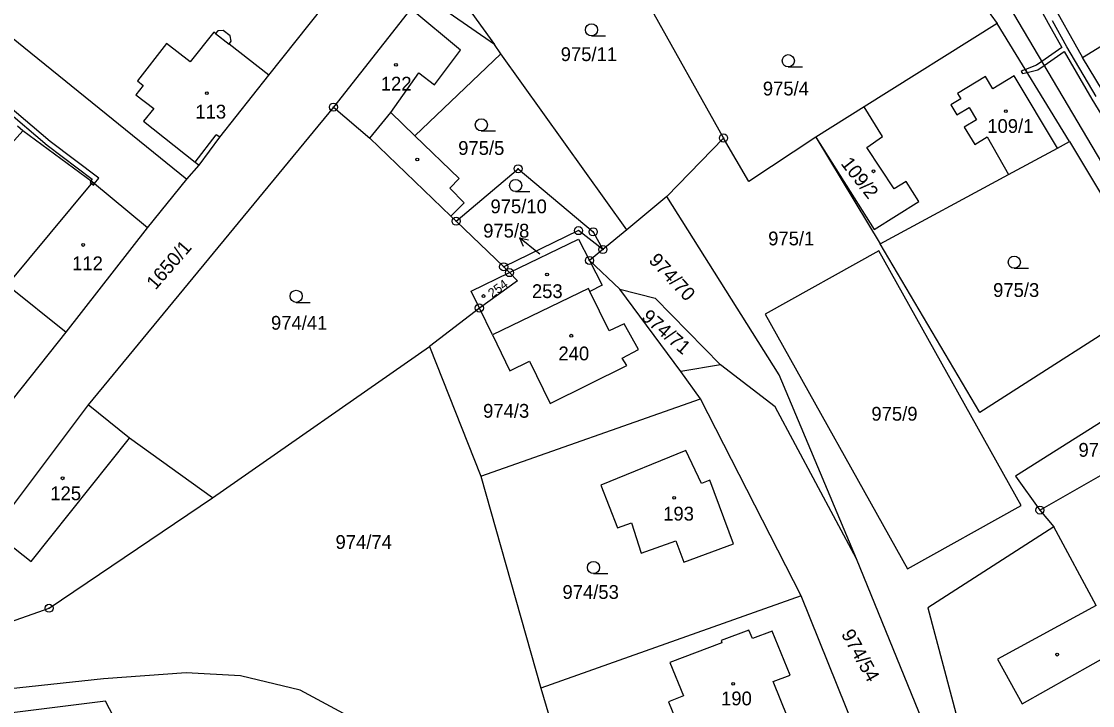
# Model space of a CAD drawing. Extents: x -680203 to -673936, y -1102717 to -1093650.
# Drawn here: x -676795.2 to -676663.1, y -1100824.1 to -1100739.7 of the extents above; entities that cross this region are included whole.
import ezdxf

# ---------------------------------------------------------------- set-up
doc = ezdxf.new("R2010")
doc.units = 0
for name, color, linetype in [('SOxx02xx_Koleje_param další_Popis10', 7, 'Continuous'), ('SOxx02xx_Staničení_Popis10', 7, 'Continuous'), ('SOxxxxxx_Koleje_hlavní_body_Popis10', 7, 'Continuous'), ('SOxxxxxx_Koleje_LN_parametry_Popis10', 7, 'Continuous'), ('SOxxxxxx_Koleje_param další_Popis10', 7, 'Continuous'), ('SOxxxxxx_Osa_bod_P', 7, 'Continuous'), ('SOxxxxxx_Staničení_Popis10', 7, 'Continuous'), ('x_prac', 7, 'Continuous')]:
    doc.layers.add(name, color=color, linetype=linetype)

msp = doc.modelspace()

# ---------------------------------------------------------------- linework, layer by layer
at = {"layer": 'SOxx02xx_Koleje_param další_Popis10'}
for centre, radius in [((-676756.77, -1100750.3), 0.5), ((-676756.77, -1100750.3), 0.0303), ((-676708.66, -1100754.11), 0.5), ((-676708.66, -1100754.11), 0.0303), ((-676733.99, -1100757.9), 0.5), ((-676733.99, -1100757.9), 0.0303), ((-676741.63, -1100764.37), 0.5), ((-676741.63, -1100764.37), 0.0303), ((-676726.54, -1100765.53), 0.5), ((-676726.54, -1100765.53), 0.0303), ((-676724.74, -1100765.68), 0.5), ((-676724.74, -1100765.68), 0.0303), ((-676723.54, -1100767.86), 0.5), ((-676725.19, -1100769.21), 0.5), ((-676723.54, -1100767.86), 0.0303), ((-676735.77, -1100769.99), 0.5), ((-676735.77, -1100769.99), 0.0303), ((-676735.05, -1100770.71), 0.5), ((-676725.19, -1100769.21), 0.0303), ((-676735.05, -1100770.71), 0.0303), ((-676738.77, -1100775.08), 0.5), ((-676738.77, -1100775.08), 0.0303), ((-676669.64, -1100800), 0.5), ((-676669.64, -1100800), 0.0303), ((-676791.84, -1100812.1), 0.5), ((-676791.84, -1100812.1), 0.0303)]:
    msp.add_circle(centre, radius, dxfattribs=at)
at = {"layer": 'SOxx02xx_Staničení_Popis10'}
for p, q in [((-676731.48, -1100768.3), (-676733.81, -1100766.41)), ((-676733.81, -1100766.41), (-676732.72, -1100766.65)), ((-676733.81, -1100766.41), (-676733.35, -1100767.43)), ((-676731.33, -1100768.42), (-676731.48, -1100768.3))]:
    msp.add_line(p, q, dxfattribs=at)
at = {"layer": 'SOxxxxxx_Koleje_hlavní_body_Popis10'}
for p, q in [((-676724.95, -1100741.52), (-676723.2, -1100741.52)), ((-676700.67, -1100745.33), (-676698.92, -1100745.33)), ((-676738.53, -1100753.23), (-676736.78, -1100753.23)), ((-676734.3, -1100760.72), (-676732.55, -1100760.72)), ((-676672.8, -1100770.18), (-676671.05, -1100770.18)), ((-676761.37, -1100774.38), (-676759.62, -1100774.38)), ((-676724.69, -1100807.82), (-676722.94, -1100807.82))]:
    msp.add_line(p, q, dxfattribs=at)
for centre in [(-676724.95, -1100740.77), (-676700.67, -1100744.58), (-676738.53, -1100752.48), (-676734.3, -1100759.97), (-676672.8, -1100769.43), (-676761.37, -1100773.63), (-676724.69, -1100807.07)]:
    msp.add_circle(centre, 0.75, dxfattribs=at)
at = {"layer": 'SOxxxxxx_Koleje_LN_parametry_Popis10'}
for points in [[(-676672.83, -1100732.25), (-676668.62, -1100739.94), (-676666.95, -1100742.94), (-676669.39, -1100744.66), (-676670.07, -1100745.13), (-676671.43, -1100745.66), (-676671.22, -1100746.01), (-676669.89, -1100745.71), (-676669.1, -1100745.15), (-676666.65, -1100743.46), (-676663.22, -1100749.32), (-676658.86, -1100756.42)], [(-676662.7, -1100749.01), (-676666.3, -1100742.87), (-676668.09, -1100739.65)], [(-676797.38, -1100750.47), (-676792.08, -1100755), (-676786.54, -1100759.19), (-676786.68, -1100759.4), (-676786.47, -1100759.55), (-676786.24, -1100759.74), (-676785.7, -1100759.07), (-676791.7, -1100754.54), (-676796.96, -1100750.05)]]:
    msp.add_lwpolyline(points, dxfattribs=at)
for points in [[(-676671.43, -1100745.66), (-676671.73, -1100745.77), (-676671.93, -1100745.89), (-676671.78, -1100746.14), (-676671.22, -1100746.01)], [(-676786.37, -1100759.91), (-676786.24, -1100759.74), (-676786.47, -1100759.55), (-676786.68, -1100759.4), (-676786.79, -1100759.58)]]:
    msp.add_lwpolyline(points, close=True, dxfattribs=at)
at = {"layer": 'SOxxxxxx_Koleje_param další_Popis10'}
for centre in [(-676749.06, -1100745.08), (-676772.38, -1100748.57), (-676673.84, -1100750.79), (-676746.43, -1100756.76), (-676690.17, -1100758.21), (-676787.63, -1100767.3), (-676730.42, -1100770.95), (-676738.26, -1100773.6), (-676727.43, -1100778.49), (-676790.17, -1100796.08), (-676714.75, -1100798.48), (-676667.52, -1100817.82), (-676707.46, -1100821.42)]:
    msp.add_circle(centre, 0.175, dxfattribs=at)
at = {"layer": 'SOxxxxxx_Staničení_Popis10'}
for p, q in [((-676741.08, -1100743.29), (-676747.24, -1100738.19)), ((-676771.3, -1100741.23), (-676769.64, -1100742.54)), ((-676744.31, -1100747.56), (-676741.08, -1100743.29)), ((-676749.71, -1100750.95), (-676746.22, -1100746.09)), ((-676746.22, -1100746.09), (-676744.31, -1100747.56)), ((-676672.83, -1100746.43), (-676675.45, -1100748.04)), ((-676667.45, -1100755.37), (-676672.83, -1100746.43)), ((-676676.36, -1100746.53), (-676679.81, -1100748.62)), ((-676675.45, -1100748.04), (-676676.36, -1100746.53)), ((-676679.81, -1100748.62), (-676679.41, -1100749.28)), ((-676679.41, -1100749.28), (-676680.64, -1100750.02)), ((-676680.64, -1100750.02), (-676679.9, -1100751.25)), ((-676679.9, -1100751.25), (-676678.37, -1100750.33)), ((-676678.37, -1100750.33), (-676677.45, -1100751.85)), ((-676752.3, -1100754.11), (-676749.71, -1100750.95)), ((-676749.71, -1100750.95), (-676746.71, -1100753.84)), ((-676677.45, -1100751.85), (-676678.97, -1100752.78)), ((-676678.97, -1100752.78), (-676677.68, -1100754.92)), ((-676773.83, -1100757.08), (-676771.23, -1100753.7)), ((-676770.77, -1100754.02), (-676771.23, -1100753.7)), ((-676677.68, -1100754.92), (-676676.13, -1100753.98)), ((-676676.13, -1100753.98), (-676673.52, -1100758.62)), ((-676786.47, -1100759.55), (-676796.99, -1100772.21)), ((-676796.99, -1100772.21), (-676789.75, -1100778.06)), ((-676794.04, -1100806.34), (-676781.93, -1100791.12)), ((-676798.77, -1100802.64), (-676794.04, -1100806.34)), ((-676662.7, -1100811.75), (-676674.85, -1100818.37)), ((-676671.83, -1100823.9), (-676659.84, -1100817.11)), ((-676674.85, -1100818.37), (-676671.83, -1100823.9))]:
    msp.add_line(p, q, dxfattribs=at)
at = {"layer": 'x_prac'}
for p, q in [((-676645.24, -1100785.51), (-676704.94, -1100684.52)), ((-676672.75, -1100729.17), (-676664.39, -1100744.2)), ((-676682.05, -1100730.15), (-676674.9, -1100740)), ((-676743.39, -1100733.54), (-676736.92, -1100742.59)), ((-676736.92, -1100742.59), (-676745.79, -1100736.42)), ((-676764.75, -1100746.35), (-676758.01, -1100737.87)), ((-676717.81, -1100737.78), (-676708.66, -1100754.11)), ((-676798.35, -1100740.16), (-676774.83, -1100759.18)), ((-676674.9, -1100740), (-676691.3, -1100750.27)), ((-676665.98, -1100754.56), (-676674.9, -1100740)), ((-676764.75, -1100746.35), (-676769.64, -1100742.54)), ((-676746.71, -1100753.84), (-676736.12, -1100743.71)), ((-676736.12, -1100743.71), (-676736.92, -1100742.59)), ((-676720.6, -1100765.42), (-676736.12, -1100743.71)), ((-676658.76, -1100753.5), (-676664.39, -1100744.2)), ((-676756.77, -1100750.3), (-676787, -1100787.02)), ((-676691.3, -1100750.27), (-676697.26, -1100753.99)), ((-676795.08, -1100753.24), (-676795.72, -1100752.64)), ((-676795.08, -1100753.24), (-676813.48, -1100773.66)), ((-676708.66, -1100754.11), (-676715.65, -1100761.31)), ((-676697.26, -1100753.99), (-676689.32, -1100767.17)), ((-676774.83, -1100759.18), (-676773.33, -1100757.46)), ((-676741.63, -1100764.37), (-676733.99, -1100757.9)), ((-676733.99, -1100757.9), (-676724.74, -1100765.68)), ((-676779.69, -1100765.2), (-676774.83, -1100759.18)), ((-676715.65, -1100761.31), (-676720.6, -1100765.42)), ((-676741.63, -1100764.37), (-676742.27, -1100763.74)), ((-676735.77, -1100769.99), (-676741.63, -1100764.37)), ((-676724.74, -1100765.68), (-676723.54, -1100767.86)), ((-676720.6, -1100765.42), (-676723.54, -1100767.86)), ((-676723.54, -1100767.86), (-676725.19, -1100769.21)), ((-676735.05, -1100770.71), (-676735.77, -1100769.99)), ((-676721.45, -1100772.74), (-676725.19, -1100769.21)), ((-676713.93, -1100782.89), (-676721.45, -1100772.74)), ((-676738.77, -1100775.08), (-676744.94, -1100779.84)), ((-676737.17, -1100778.38), (-676738.77, -1100775.08)), ((-676771.7, -1100798.48), (-676744.94, -1100779.84)), ((-676744.94, -1100779.84), (-676738.6, -1100795.82)), ((-676709.03, -1100782.09), (-676713.93, -1100782.89)), ((-676711.48, -1100786.26), (-676713.93, -1100782.89)), ((-676738.6, -1100795.82), (-676711.48, -1100786.26)), ((-676699.1, -1100810.57), (-676711.48, -1100786.26)), ((-676669.64, -1100800), (-676647.25, -1100787.16)), ((-676738.6, -1100795.82), (-676731.18, -1100821.98)), ((-676669.64, -1100800), (-676667.93, -1100802.08)), ((-676662.7, -1100811.75), (-676667.93, -1100802.08)), ((-676676.06, -1100845.73), (-676692.24, -1100806.01)), ((-676699.1, -1100810.57), (-676731.18, -1100821.98)), ((-676690.51, -1100831.84), (-676699.1, -1100810.57)), ((-676731.18, -1100821.98), (-676724.81, -1100843.45))]:
    msp.add_line(p, q, dxfattribs=at)
for points in [[(-676664.39, -1100744.2), (-676647.73, -1100733.89), (-676652.22, -1100726.48), (-676655.94, -1100720.27)], [(-676745.79, -1100736.42), (-676747.24, -1100738.19), (-676756.77, -1100750.3)], [(-676771.3, -1100741.23), (-676771.54, -1100741.05), (-676774.45, -1100744.72), (-676777.34, -1100742.46), (-676780.95, -1100747.06), (-676780.22, -1100747.63), (-676781.13, -1100748.78), (-676778.93, -1100750.47), (-676780.18, -1100752.05), (-676773.83, -1100757.08), (-676773.33, -1100757.46)], [(-676769.64, -1100742.54), (-676769.39, -1100742.18), (-676769.49, -1100741.52), (-676770.37, -1100740.83), (-676771.04, -1100740.9), (-676771.3, -1100741.23)], [(-676773.33, -1100757.46), (-676770.77, -1100754.02), (-676764.75, -1100746.35)], [(-676756.77, -1100750.3), (-676752.3, -1100754.11), (-676742.27, -1100763.74)], [(-676697.26, -1100753.99), (-676690.07, -1100765.4), (-676684.58, -1100761.93), (-676686.14, -1100759.48), (-676687.61, -1100760.38), (-676690.98, -1100755.29), (-676689.04, -1100753.93), (-676691.3, -1100750.27)], [(-676779.69, -1100765.2), (-676786.47, -1100759.55), (-676795.08, -1100753.24)], [(-676742.27, -1100763.74), (-676740.64, -1100762.1), (-676742.43, -1100760.31), (-676741.25, -1100759.09), (-676746.71, -1100753.84)], [(-676697.26, -1100753.99), (-676705.52, -1100759.47), (-676708.66, -1100754.11)], [(-676689.32, -1100767.17), (-676673.52, -1100758.62), (-676667.45, -1100755.37), (-676665.98, -1100754.56)], [(-676665.98, -1100754.56), (-676654.55, -1100773.58), (-676677.03, -1100787.96), (-676689.32, -1100767.17)], [(-676692.24, -1100806.01), (-676701.81, -1100783.31), (-676715.65, -1100761.31)], [(-676797.35, -1100787.64), (-676789.75, -1100778.06), (-676779.69, -1100765.2)], [(-676723.54, -1100767.86), (-676726.54, -1100765.53), (-676735.77, -1100769.99)], [(-676735.05, -1100770.71), (-676726.55, -1100766.57), (-676725.19, -1100769.21)], [(-676689.52, -1100768.02), (-676703.52, -1100775.84), (-676685.95, -1100807.24), (-676671.93, -1100799.43), (-676689.52, -1100768.02)], [(-676725.19, -1100769.21), (-676723.64, -1100772.25), (-676725.15, -1100773.04)], [(-676738.77, -1100775.08), (-676739.78, -1100773.01), (-676735.05, -1100770.71)], [(-676735.05, -1100770.71), (-676734.06, -1100771.71), (-676738.77, -1100775.08)], [(-676725.15, -1100773.04), (-676725.32, -1100772.68), (-676737.17, -1100778.38)], [(-676721.45, -1100772.74), (-676717.08, -1100773.85), (-676709.03, -1100782.09)], [(-676737.17, -1100778.38), (-676735.01, -1100782.83), (-676732.57, -1100781.64), (-676730.04, -1100786.84), (-676720.59, -1100782.18), (-676721.14, -1100781.26), (-676719.15, -1100780.18), (-676720.92, -1100777.01), (-676722.75, -1100777.91), (-676725.15, -1100773.04)], [(-676692.24, -1100806.01), (-676702.28, -1100787.27), (-676709.03, -1100782.09)], [(-676656.37, -1100785.52), (-676672.63, -1100795.8), (-676669.64, -1100800)], [(-676787, -1100787.02), (-676798.77, -1100802.64), (-676805.62, -1100810.46), (-676813.73, -1100819.81)], [(-676771.7, -1100798.48), (-676781.93, -1100791.12), (-676787, -1100787.02)], [(-676723.81, -1100796.92), (-676721.72, -1100802.2), (-676720.01, -1100801.56), (-676718.8, -1100805.32), (-676714.54, -1100803.8), (-676713.56, -1100806.42), (-676707.44, -1100804.18), (-676710.33, -1100796.32), (-676711.39, -1100796.7), (-676713.29, -1100792.63), (-676723.81, -1100796.92)], [(-676813.73, -1100819.81), (-676791.84, -1100812.1), (-676771.7, -1100798.48)], [(-676667.93, -1100802.08), (-676683.46, -1100812.04), (-676678.82, -1100829.53), (-676676.79, -1100829.08), (-676676.19, -1100830.3), (-676671.54, -1100844.46)], [(-676708.97, -1100816.1), (-676708.85, -1100816.39), (-676715.26, -1100818.81), (-676713.58, -1100822.92), (-676715.45, -1100823.63), (-676712.76, -1100830.2), (-676700.72, -1100825.62), (-676702.54, -1100821.16), (-676700.43, -1100820.37), (-676702.66, -1100814.93), (-676705.09, -1100815.84), (-676705.52, -1100814.8), (-676708.97, -1100816.1)], [(-676730.8, -1100870.87), (-676736.06, -1100854.01), (-676742.65, -1100840.34), (-676736.87, -1100837.45), (-676738.04, -1100834.98), (-676744.06, -1100837.76), (-676746.8, -1100833.39), (-676749.81, -1100829.32), (-676752.86, -1100826.51), (-676760.89, -1100822.22), (-676768.22, -1100820.45), (-676774.95, -1100820.06), (-676785.11, -1100820.83), (-676817.64, -1100824.3)], [(-676771.21, -1100849.78), (-676784.88, -1100823.57), (-676821.09, -1100828.1)]]:
    msp.add_lwpolyline(points, dxfattribs=at)

# ---------------------------------------------------------------- texts
at = {"layer": 'SOxxxxxx_Osa_bod_P'}
for s, p in [('975/11', (-676728.74, -1100744.62)), ('122', (-676750.93, -1100748.26)), ('975/4', (-676703.81, -1100748.86)), ('113', (-676773.8, -1100751.71)), ('109/1', (-676676.13, -1100753.48)), ('975/5', (-676741.38, -1100756.19)), ('975/10', (-676737.4, -1100763.39)), ('975/8', (-676738.3, -1100766.39)), ('975/1', (-676703.15, -1100767.35)), ('112', (-676789, -1100770.42)), ('253', (-676732.29, -1100773.85)), ('975/3', (-676675.41, -1100773.71)), ('974/41', (-676764.47, -1100777.75)), ('240', (-676729.02, -1100781.53)), ('974/3', (-676738.31, -1100788.61)), ('975/9', (-676690.42, -1100788.97)), ('975/7', (-676664.88, -1100793.42)), ('125', (-676791.69, -1100798.78)), ('193', (-676716.1, -1100801.29)), ('974/74', (-676756.51, -1100804.79)), ('974/53', (-676728.52, -1100810.95)), ('190', (-676708.96, -1100824.08))]:
    msp.add_text(s, height=1.7, dxfattribs=at).set_placement(p)
for s, height, rotation, p in [('109/2', 1.7, 308, (-676694.27, -1100757.28)), ('1650/1', 1.7, 49, (-676778.71, -1100772.93)), ('974/70', 1.7, 313, (-676717.98, -1100769.28)), ('254', 1.14, 36, (-676737.18, -1100773.88)), ('974/71', 1.7, 319, (-676718.9, -1100776.37)), ('974/54', 1.7, 299, (-676694.19, -1100815.28))]:
    msp.add_text(s, height=height, rotation=rotation, dxfattribs=at).set_placement(p)

doc.saveas('drawing.dxf')
